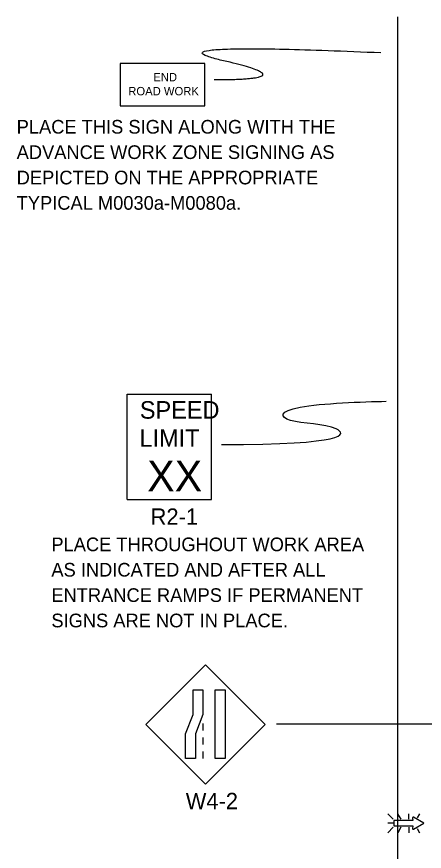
# Model space of a CAD drawing. Extents: x 16782 to 19504, y 6935 to 8243.
# Drawn here: x 17772.1 to 17980.9, y 7755.7 to 8183.3 of the extents above; entities that cross this region are included whole.
import ezdxf

# ---------------------------------------------------------------- set-up
doc = ezdxf.new("R2010")
doc.units = 0
for name, color, linetype in [('PAVT_EDGE_EX', 7, 'Continuous'), ('TRAFFIC_SIGNS_PR', 7, 'Continuous'), ('TYPICAL_TEXT_DIMEN_PR', 7, 'Continuous')]:
    doc.layers.add(name, color=color, linetype=linetype)

msp = doc.modelspace()

# ---------------------------------------------------------------- linework, layer by layer
at = {"layer": 'PAVT_EDGE_EX'}
msp.add_line((17967.13, 8183.26), (17967.13, 7404.46), dxfattribs=at)
at = {"layer": 'TRAFFIC_SIGNS_PR'}
for p, q in [((17828.73, 7989.85), (17871.93, 7989.85)), ((17828.73, 7935.85), (17828.73, 7989.85)), ((17871.93, 7935.85), (17871.93, 7989.85)), ((17828.73, 7935.85), (17871.93, 7935.85)), ((17868.9, 7851.25), (17838.36, 7820.7)), ((17899.45, 7820.7), (17868.9, 7851.25)), ((17838.36, 7820.7), (17868.9, 7790.15)), ((17867.5, 7821.25), (17867.5, 7817.65)), ((17868.9, 7790.15), (17899.45, 7820.7)), ((17867.5, 7814.05), (17867.5, 7810.45)), ((17867.5, 7806.85), (17867.5, 7803.25)), ((17964.96, 7772.11), (17962.14, 7774.93)), ((17967.25, 7774.93), (17968.88, 7772.11)), ((17973.04, 7772.11), (17973.04, 7774.93)), ((17978.51, 7774.93), (17977.3, 7772.84)), ((17964.96, 7770.08), (17962.14, 7770.08)), ((17964.96, 7768.04), (17962.14, 7765.22)), ((17968.91, 7768.04), (17967.28, 7765.22)), ((17973.04, 7768.04), (17973.04, 7765.22)), ((17977.22, 7767.41), (17978.49, 7765.22))]:
    msp.add_line(p, q, dxfattribs=at)
for points in [[(17825.22, 8137.62), (17868.42, 8137.62), (17868.42, 8159.22), (17825.22, 8159.22)], [(17867.5, 7838.41), (17867.5, 7825.83), (17863.74, 7815.83), (17863.74, 7803.25), (17858.68, 7803.25), (17858.68, 7815.83), (17862.45, 7825.83), (17862.45, 7838.41)], [(17878.9, 7838.41), (17878.9, 7803.25), (17873.85, 7803.25), (17873.85, 7838.41)]]:
    msp.add_lwpolyline(points, close=True, dxfattribs=at)
for points in [[(17975.37, 7767.06), (17980.68, 7770.08), (17975.37, 7773.12)], [(17974.87, 7772.76), (17975.1, 7771.46), (17965.38, 7771.46), (17965.38, 7768.72), (17975.1, 7768.72), (17974.87, 7767.41)]]:
    msp.add_lwpolyline(points, dxfattribs=at)
for centre, start, end in [((17975.2, 7772.82), 61.4833, 189.9593), ((17975.2, 7767.36), 170.7308, 298.8916)]:
    msp.add_arc(centre, 0.341, start, end, dxfattribs=at)
at = {"layer": 'TYPICAL_TEXT_DIMEN_PR'}
msp.add_line((17905.13, 7820.93), (17987.32, 7820.93), dxfattribs=at)
for points, degree in [([(17873.34, 8151.01), (17920.58, 8151.01), (17835.56, 8170.36), (17958.65, 8164.87)], 2), ([(17876.97, 7964.05), (17941.55, 7964.05), (17941.55, 7974.81), (17906.63, 7974.81), (17906.63, 7984.47), (17949.49, 7985.99), (17961.4, 7986.25)], 3)]:
    msp.add_open_spline(points, degree=degree, dxfattribs=at)

# ---------------------------------------------------------------- texts
at = {"layer": 'TRAFFIC_SIGNS_PR'}
for s, height, p in [('END', 4.31, (17842.1, 8150.14)), ('ROAD WORK', 4.31, (17829.28, 8142.96)), ('PLACE THIS SIGN ALONG WITH THE', 7, (17772.13, 8123.36)), ('ADVANCE WORK ZONE SIGNING AS', 7, (17772.13, 8110.36)), ('DEPICTED ON THE APPROPRIATE', 7, (17772.13, 8097.36)), ('TYPICAL M0030a-M0080a.', 7, (17772.13, 8084.36)), ('SPEED', 9, (17835.21, 7977.32)), ('LIMIT', 9, (17835.03, 7962.92)), ('XX', 15.785, (17838.98, 7940.08)), ('R2-1', 8.37, (17840.74, 7922.98)), ('PLACE THROUGHOUT WORK AREA', 7, (17789.9, 7909.44)), ('AS INDICATED AND AFTER ALL', 7, (17789.9, 7896.44)), ('ENTRANCE RAMPS IF PERMANENT', 7, (17789.9, 7883.44)), ('SIGNS ARE NOT IN PLACE.', 7, (17789.9, 7870.44)), ('W4-2', 8.37, (17858.73, 7777.28))]:
    msp.add_text(s, height=height, dxfattribs=at).set_placement(p)

doc.saveas('drawing.dxf')
